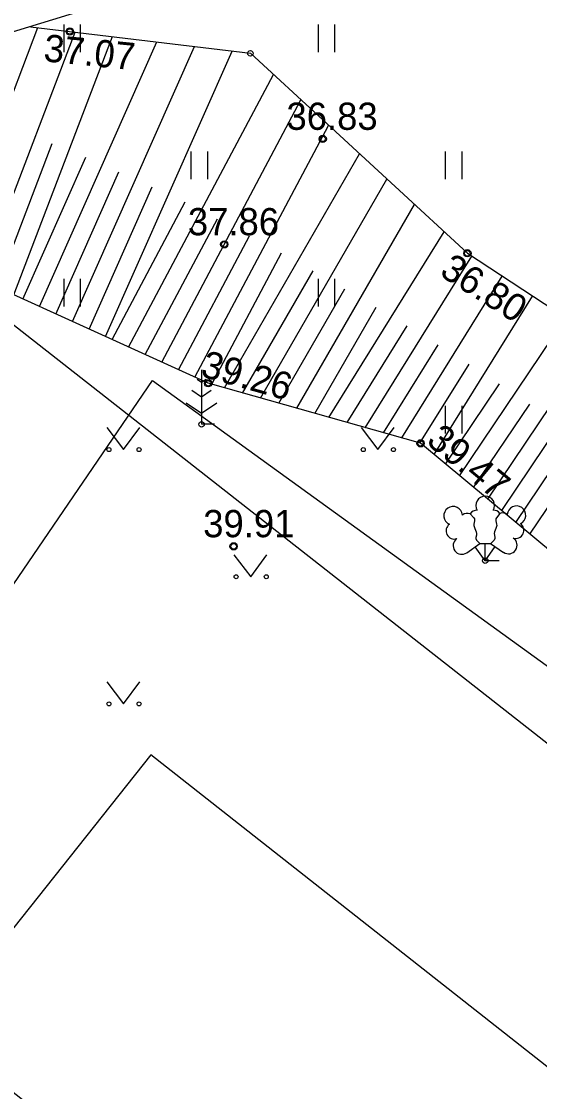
# Model space of a CAD drawing. Extents: x 641898 to 642452, y 6471715 to 6472255.
# Drawn here: x 642024.06 to 642038.32, y 6472085.4 to 6472114.87 of the extents above; entities that cross this region are included whole.
import ezdxf

# ---------------------------------------------------------------- set-up
doc = ezdxf.new("R2010")
doc.units = 0
for name, color, linetype in [('HALJASTUS', 7, 'Continuous'), ('HOONE', 7, 'Continuous'), ('KORGUS-EH2000', 7, 'Continuous'), ('MOOTMPUNKT', 7, 'Continuous'), ('MOOTPIIR', 7, 'Continuous'), ('PIIR', 7, 'Continuous'), ('PUU', 7, 'Continuous'), ('RELJEEF', 7, 'Continuous')]:
    doc.layers.add(name, color=color, linetype=linetype)

msp = doc.modelspace()

# ---------------------------------------------------------------- linework, layer by layer
at = {"layer": 'HALJASTUS'}
for p, q in [((642025.225, 6472114.782), (642025.225, 6472114.021)), ((642025.68, 6472114.782), (642025.68, 6472114.021)), ((642032.225, 6472114.782), (642032.225, 6472114.021)), ((642032.68, 6472114.782), (642032.68, 6472114.021)), ((642028.725, 6472111.282), (642028.725, 6472110.521)), ((642029.18, 6472111.282), (642029.18, 6472110.521)), ((642035.725, 6472111.282), (642035.725, 6472110.521)), ((642036.18, 6472111.282), (642036.18, 6472110.521)), ((642025.225, 6472107.782), (642025.225, 6472107.021)), ((642025.68, 6472107.782), (642025.68, 6472107.021)), ((642032.225, 6472107.782), (642032.225, 6472107.021)), ((642032.68, 6472107.782), (642032.68, 6472107.021)), ((642035.725, 6472104.282), (642035.725, 6472103.521)), ((642036.18, 6472104.282), (642036.18, 6472103.521)), ((642026.408, 6472103.682), (642026.871, 6472103.075)), ((642026.871, 6472103.075), (642027.317, 6472103.682)), ((642033.408, 6472103.682), (642033.871, 6472103.075)), ((642033.871, 6472103.075), (642034.317, 6472103.682)), ((642029.908, 6472100.182), (642030.371, 6472099.575)), ((642030.371, 6472099.575), (642030.817, 6472100.182)), ((642026.408, 6472096.682), (642026.871, 6472096.075)), ((642026.871, 6472096.075), (642027.317, 6472096.682))]:
    msp.add_line(p, q, dxfattribs=at)
for centre in [(642026.47, 6472103.075), (642027.299, 6472103.075), (642033.47, 6472103.075), (642034.299, 6472103.075), (642029.97, 6472099.575), (642030.799, 6472099.575), (642026.47, 6472096.075), (642027.299, 6472096.075)]:
    msp.add_circle(centre, 0.055, dxfattribs=at)
at = {"layer": 'HOONE'}
msp.add_lwpolyline([(642065.653, 6472064.719), (642027.624, 6472094.67), (642021.622, 6472087.119), (642059.651, 6472057.168), (642065.653, 6472064.719)], dxfattribs=at)
at = {"layer": 'KORGUS-EH2000'}
for centre in [(642025.394, 6472114.59), (642032.353, 6472111.631), (642029.644, 6472108.728), (642036.333, 6472108.482), (642029.201, 6472104.902), (642035.046, 6472103.249), (642029.901, 6472100.413)]:
    msp.add_circle(centre, 0.1, dxfattribs=at)
at = {"layer": 'MOOTMPUNKT'}
for centre in [(642025.394, 6472114.59), (642030.362, 6472113.989), (642032.353, 6472111.631), (642029.644, 6472108.728), (642036.333, 6472108.482), (642029.201, 6472104.902), (642029.018, 6472103.773), (642035.046, 6472103.249), (642029.901, 6472100.413), (642036.825, 6472100.017)]:
    msp.add_circle(centre, 0.075, dxfattribs=at)
at = {"layer": 'MOOTPIIR'}
msp.add_lwpolyline([(642014.306, 6472085.384), (642027.67, 6472104.979), (642055.501, 6472084.843), (642081.563, 6472094.262), (642123.938, 6472142.273), (642065.721, 6472244.475), (642008.922, 6472196.948), (642003.347, 6472200.453), (641979.65, 6472162.756), (641979.65, 6472162.756), (641986.045, 6472158.736), (642004.269, 6472142.365), (641987.048, 6472123.488), (641970.482, 6472097.889), (641986.758, 6472084.396)], close=True, dxfattribs=at)
at = {"layer": 'PIIR'}
msp.add_line((642016.19, 6472112.51), (642089.96, 6472054.66), dxfattribs=at)
at = {"layer": 'PUU'}
for p, q in [((642029.018, 6472105.273), (642029.018, 6472103.773)), ((642029.018, 6472104.923), (642028.894, 6472105.006)), ((642029.142, 6472105.006), (642029.018, 6472104.923)), ((642029.018, 6472104.523), (642028.751, 6472104.701)), ((642029.285, 6472104.701), (642029.018, 6472104.523)), ((642028.594, 6472104.362), (642029.018, 6472104.08)), ((642029.018, 6472104.08), (642029.442, 6472104.362)), ((642029.378, 6472103.773), (642029.018, 6472103.773)), ((642036.315, 6472100.237), (642036.675, 6472100.492)), ((642036.825, 6472100.017), (642036.55, 6472100.402)), ((642036.675, 6472100.492), (642036.97, 6472100.492)), ((642036.825, 6472100.017), (642036.825, 6472100.492)), ((642036.825, 6472100.017), (642037.095, 6472100.407)), ((642036.97, 6472100.492), (642037.33, 6472100.247)), ((642037.205, 6472100.017), (642036.825, 6472100.017))]:
    msp.add_line(p, q, dxfattribs=at)
for points in [[(642036.412, 6472101.304), (642036.515, 6472101.202), (642036.53, 6472101.172), (642036.53, 6472101.117), (642036.515, 6472101.027), (642036.515, 6472100.982), (642036.535, 6472100.902), (642036.575, 6472100.812), (642036.585, 6472100.767), (642036.58, 6472100.722), (642036.565, 6472100.657), (642036.565, 6472100.627), (642036.585, 6472100.587), (642036.61, 6472100.557), (642036.675, 6472100.492)], [(642037.229, 6472101.318), (642037.135, 6472101.202), (642037.12, 6472101.172), (642037.12, 6472101.117), (642037.135, 6472101.027), (642037.14, 6472100.982), (642037.12, 6472100.902), (642037.08, 6472100.812), (642037.07, 6472100.767), (642037.075, 6472100.722), (642037.09, 6472100.657), (642037.09, 6472100.627), (642037.07, 6472100.587), (642037.045, 6472100.557), (642036.975, 6472100.492)]]:
    msp.add_lwpolyline(points, dxfattribs=at)
for centre, radius, start, end in [((642036.825, 6472101.537), 0.256, 90.0013, 211.0159), ((642036.825, 6472101.537), 0.256, 328.9841, 89.9987), ((642035.942, 6472101.254), 0.256, 125.5389, 246.5536), ((642035.942, 6472101.254), 0.256, 4.5218, 125.5364), ((642036.587, 6472101.205), 0.202, 84.7965, 150.2995), ((642037.062, 6472101.205), 0.202, 34.3857, 95.2035), ((642037.685, 6472101.27), 0.256, 55.522, 176.5367), ((642037.685, 6472101.27), 0.256, 294.5049, 55.5195), ((642036.328, 6472101.121), 0.202, 65.2382, 130.7412), ((642037.301, 6472101.13), 0.202, 50.3173, 111.1351), ((642035.97, 6472100.837), 0.224, 125.4667, 288.5349), ((642037.665, 6472100.852), 0.224, 252.5235, 55.5918), ((642036.179, 6472100.431), 0.237, 125.5377, 305.5366), ((642037.463, 6472100.443), 0.237, 235.5219, 55.5208)]:
    msp.add_arc(centre, radius, start, end, dxfattribs=at)
at = {"layer": 'RELJEEF'}
for p, q in [((642022.029, 6472108.167), (642024.518, 6472114.696)), ((642022.941, 6472107.752), (642025.541, 6472114.572)), ((642023.853, 6472107.337), (642026.564, 6472114.448)), ((642024.557, 6472107.016), (642027.787, 6472114.301)), ((642025.467, 6472106.602), (642028.825, 6472114.175)), ((642026.377, 6472106.188), (642029.863, 6472114.049)), ((642027.013, 6472105.898), (642030.995, 6472113.405)), ((642027.924, 6472105.483), (642031.755, 6472112.704)), ((642028.836, 6472105.068), (642032.515, 6472112.003)), ((642023.397, 6472107.544), (642024.908, 6472111.506)), ((642024.102, 6472107.223), (642025.832, 6472111.127)), ((642029.653, 6472104.774), (642033.366, 6472111.218)), ((642025.012, 6472106.809), (642026.747, 6472110.722)), ((642030.645, 6472104.494), (642034.12, 6472110.523)), ((642025.922, 6472106.395), (642027.661, 6472110.316)), ((642026.557, 6472106.106), (642028.57, 6472109.902)), ((642031.638, 6472104.213), (642034.874, 6472109.828)), ((642027.469, 6472105.691), (642029.454, 6472109.433)), ((642032.524, 6472103.962), (642035.695, 6472109.071)), ((642028.38, 6472105.276), (642030.337, 6472108.964)), ((642029.299, 6472104.874), (642031.221, 6472108.496)), ((642033.525, 6472103.679), (642036.456, 6472108.401)), ((642030.149, 6472104.634), (642032.09, 6472108.002)), ((642034.526, 6472103.396), (642037.293, 6472107.853)), ((642031.142, 6472104.353), (642032.957, 6472107.503)), ((642035.419, 6472102.939), (642038.129, 6472107.305)), ((642032.134, 6472104.073), (642033.823, 6472107.003)), ((642036.119, 6472102.358), (642039.042, 6472106.707)), ((642033.024, 6472103.821), (642034.679, 6472106.486)), ((642036.893, 6472101.716), (642039.879, 6472106.159)), ((642034.025, 6472103.538), (642035.528, 6472105.959)), ((642037.666, 6472101.073), (642040.71, 6472105.603)), ((642035.027, 6472103.254), (642036.378, 6472105.431)), ((642035.733, 6472102.679), (642037.218, 6472104.889)), ((642036.506, 6472102.037), (642038.048, 6472104.331)), ((642037.279, 6472101.395), (642038.878, 6472103.773)), ((642038.053, 6472100.752), (642039.708, 6472103.216))]:
    msp.add_line(p, q, dxfattribs=at)
for points in [[(642009.422, 6472112.742), (642011.469, 6472114.538), (642021.273, 6472119.831), (642030.743, 6472124.628), (642039.752, 6472128.982), (642050.967, 6472134.85), (642058.208, 6472138.912), (642059.402, 6472139.059), (642060.171, 6472138.313), (642060.027, 6472137.169), (642058.959, 6472136.054), (642051.674, 6472131.646), (642042.143, 6472126.699), (642035.655, 6472123.419), (642032.765, 6472119.235), (642026.028, 6472115.246), (642020.049, 6472113.422), (642015.898, 6472110.337), (642013.512, 6472106.135), (642008.467, 6472103.33), (642003.93, 6472101.516)], [(642024.308, 6472114.721), (642030.362, 6472113.989), (642036.333, 6472108.482), (642040.265, 6472105.906), (642044.229, 6472103.211), (642048.288, 6472102.29), (642050.25, 6472100.358), (642050.829, 6472098.064), (642050.8, 6472095.965), (642049.352, 6472094.247)], [(642046.898, 6472092.573), (642045.899, 6472093.597), (642045.866, 6472095.265), (642040.033, 6472099.108), (642035.046, 6472103.249), (642029.201, 6472104.902), (642019.993, 6472109.094), (642016.735, 6472110.959)]]:
    msp.add_lwpolyline(points, dxfattribs=at)

# ---------------------------------------------------------------- texts
at = {"layer": 'KORGUS-EH2000'}
for s, rotation, p in [('37.07', 354.2822, (642024.653, 6472113.772)), ('36.80', 327.6642, (642035.537, 6472107.885)), ('39.26', 344.3618, (642028.962, 6472105.1)), ('39.47', 320.3212, (642035.171, 6472103.262))]:
    msp.add_text(s, height=0.75, rotation=rotation, dxfattribs=at).set_placement(p)
for s, p in [('36.83', (642031.355, 6472111.881)), ('37.86', (642028.642, 6472108.978)), ('39.91', (642029.064, 6472100.663))]:
    msp.add_text(s, height=0.75, dxfattribs=at).set_placement(p)

doc.saveas('drawing.dxf')
